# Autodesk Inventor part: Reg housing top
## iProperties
Shininess: 64.0
Angle Display Precision: 2
Document Length Units: 11272
Document Angle Units: 11279
Document Time Units: 11290
Document Mass Units: 11286
Document Length Units Precision: 3
Document Angle Units Precision: 2
Created: 2006-10
Part Number: Reg housing top
Document SubType Name: Modeling
Designer: John Croya
Density: 1 g/cm^3
Density: 0.0
Volumn: 0.0
Area: 0.0
PropertySet Name: Model Information
Control State: 0
Master: False
Checked Out: False
Author: John Croya
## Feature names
1. Reg housing top [Revolution]
2. ASA threads
3. Middle section threads
